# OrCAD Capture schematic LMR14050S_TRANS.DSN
size Custom; title: 40V, 5A SIMPLE SWITCHER®, 2.2MHz Step-Down Regulator; note: DATASHEET:
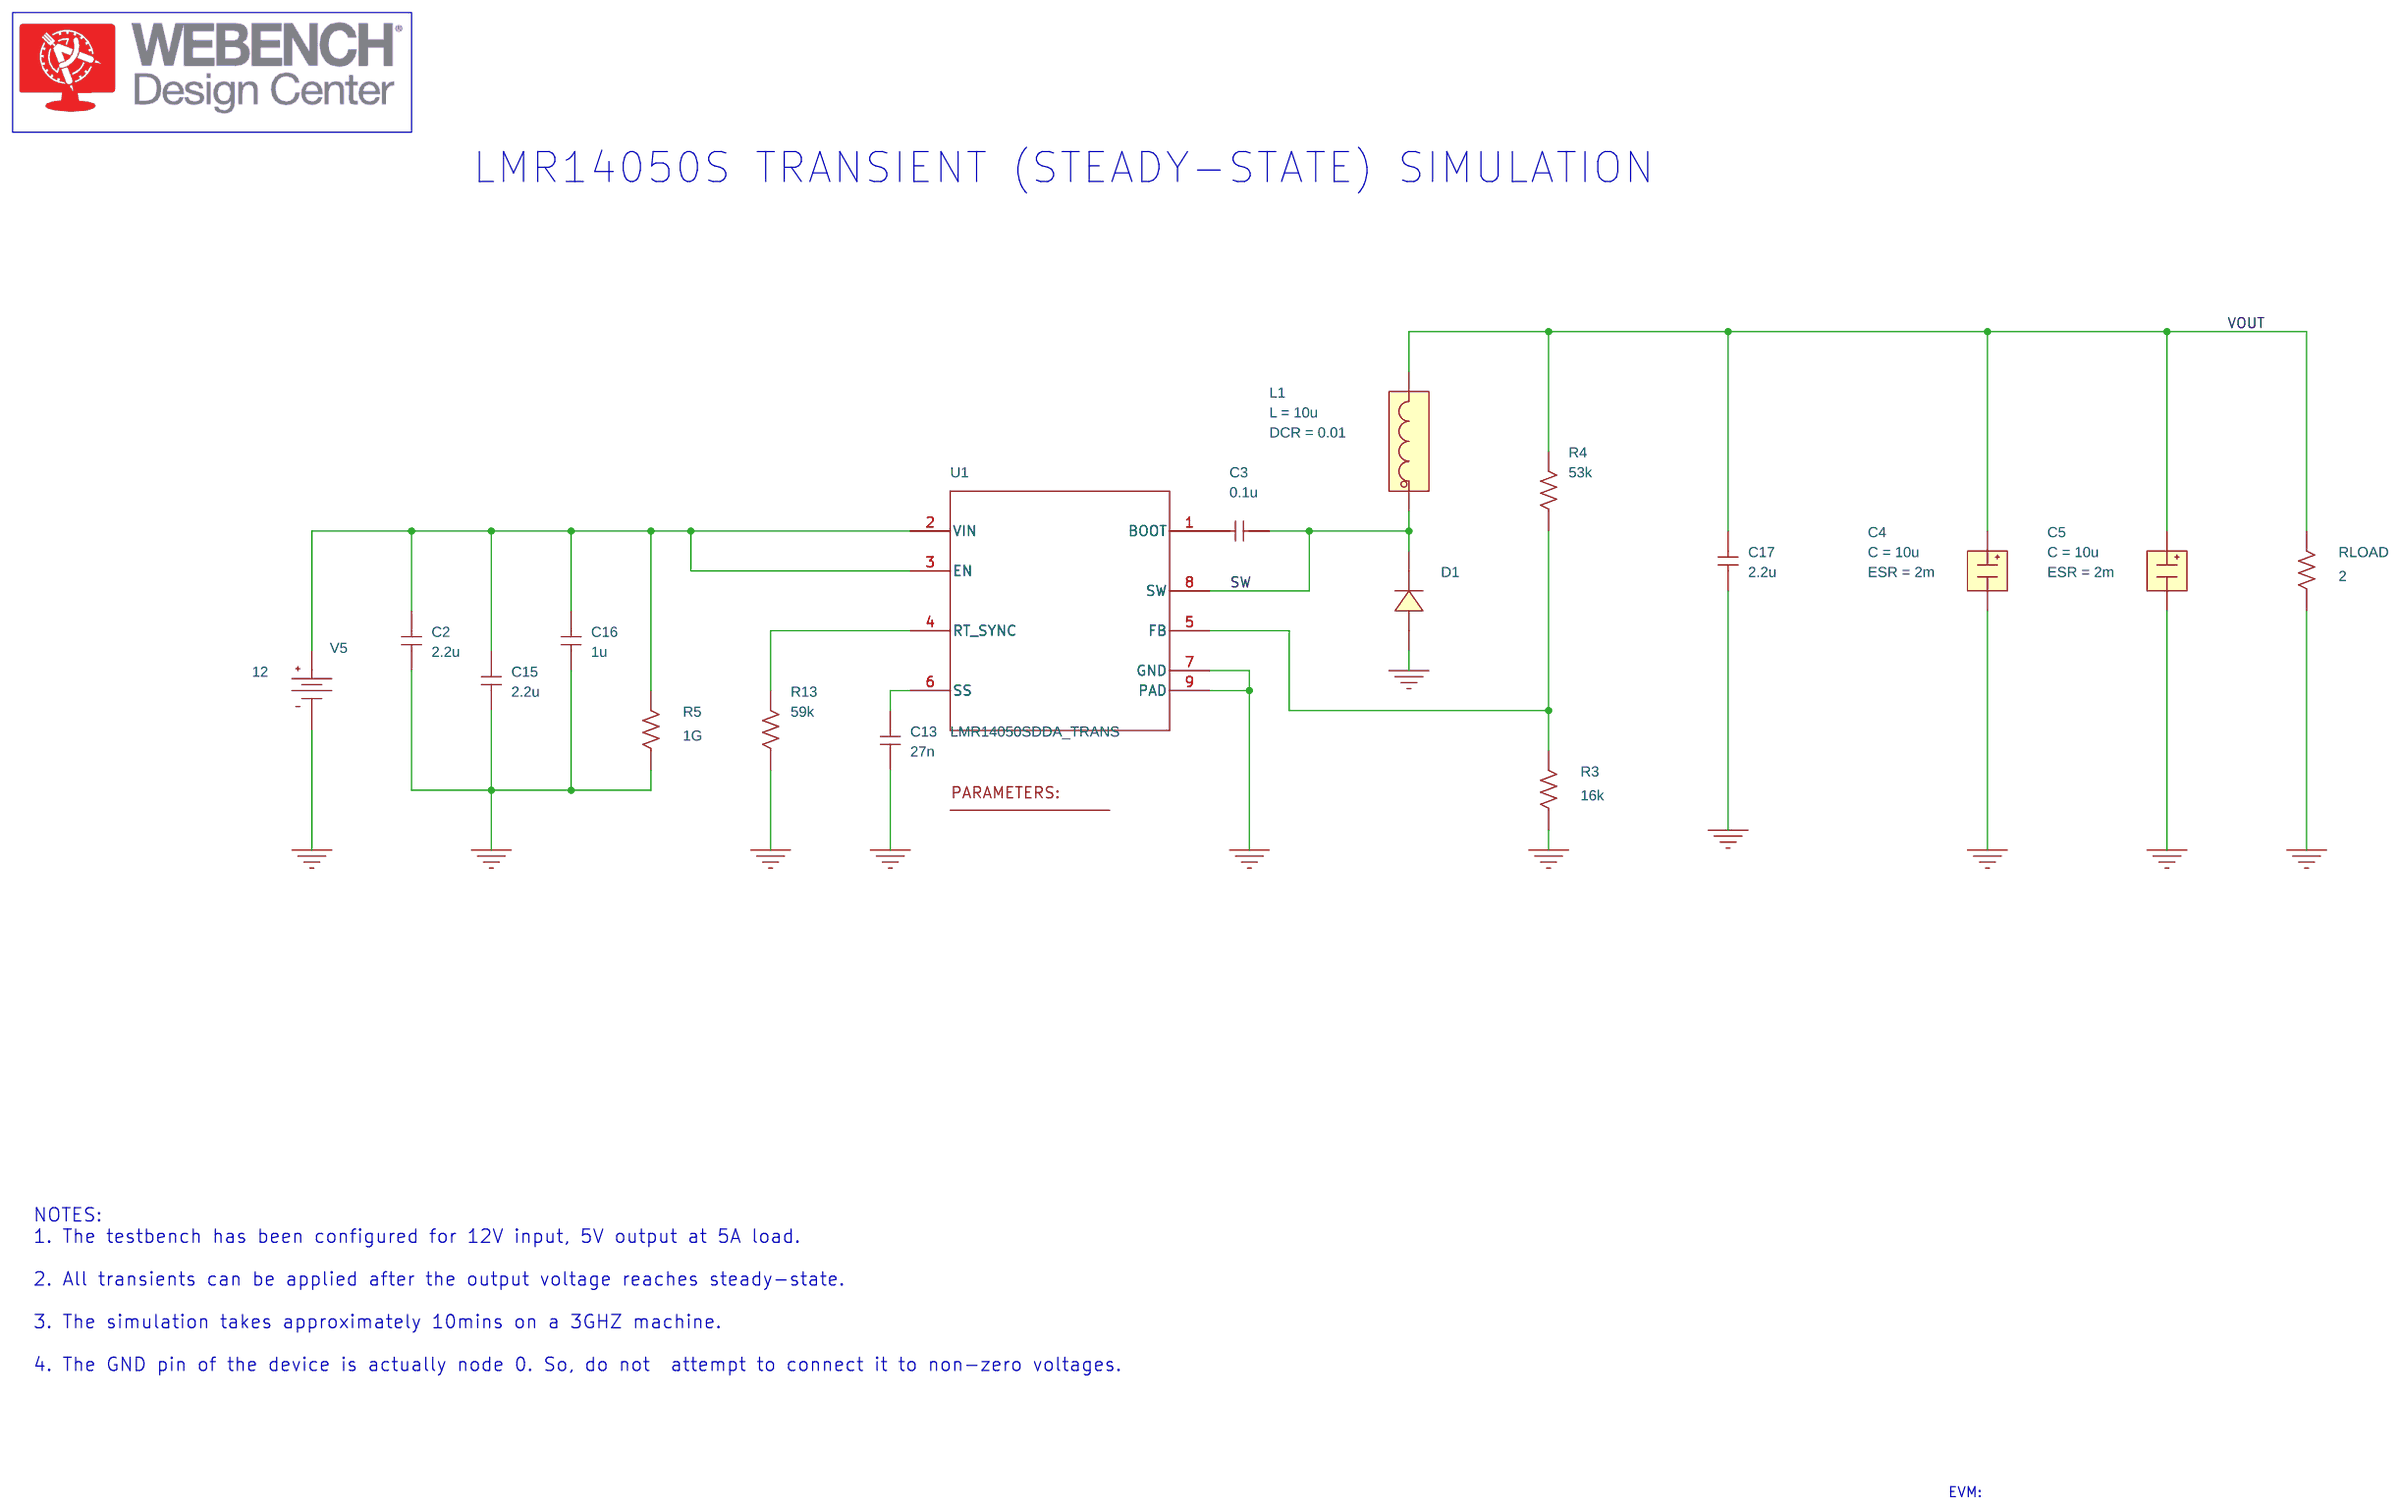
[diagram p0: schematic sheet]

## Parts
1  PARAM
C2  2.2u  [RAD/CK05]
C3  0.1u  [RAD/CK05]
C4  CESR
C5  CESR
C13  27n  [RAD/CK05]
C15  2.2u  [RAD/CK05]
C16  1u  [RAD/CK05]
C17  2.2u  [RAD/CK05]
D1  D_D1
L1  LDCR
R3  16k  [AX/RC05]
R4  53k  [AX/RC05]
R5  1G  [AX/RC05]
R13  59k  [AX/RC05]
RLOAD  2  [AX/RC05]
U1  LMR14050SDDA_TRANS  [DDA0008E]
V5  VDC

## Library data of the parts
1 = PARAM
C2 C15-C17 = C: IC: 12
C3 C13 = C
C4 C5 = CESR: C: 10u; ESR: 2m; IC: 3.2; PSpiceTemplate: X^@REFDES %IN %OUT @MODEL PARAMS:  ?C|C=@C||C=100u|  ?ESR|ESR=@ESR||ESR=0.01| ?X|X=@X||X=2|  ?IC|IC=@IC||IC=2|; X: 1
D1 = D_D1
L1 = LDCR: DCR: 0.01; IC: 0; L: 10u; PSpiceTemplate: X^@REFDES %IN %OUT @MODEL PARAMS:  ?L|L=@L||L=1u|  ?DCR|DCR=@DCR||DCR=0.01| ?IC|IC=@IC||IC=0|
R3-R5 R13 RLOAD = R
U1 = LMR14050SDDA_TRANS: PSpiceTemplate: X^@REFDES %BOOT %VIN %EN %RT_SYNC %FB %SS %GND %SW %PAD @MODEL
V5 = VDC: DC: 12

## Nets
0: C2.1 C4.3(OUT) C5.3(OUT) C13.1 C15.1 C16.1 C17.1 D1.2(A) R3.1 R5.1 R13.1 RLOAD.1 U1.7(GND) U1.9(PAD) V5.1(-)
SW: C3.1 D1.1(C) L1.1(IN) U1.8(SW)
VOUT: C4.1(IN) C5.1(IN) C17.2 L1.3(OUT) R4.2 RLOAD.2
N7516999: C13.2 U1.6(SS)
N7517075: C2.2 C15.2 C16.2 R5.2 U1.2(VIN) U1.3(EN) V5.0(+)
N7517137: R3.2 R4.1 U1.5(FB)
N14557517: R13.2 U1.4(RT_SYNC)
N16725417: C3.2 U1.1(BOOT)

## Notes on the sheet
- LMR14050S TRANSIENT (STEADY-STATE) SIMULATION
- NOTES:
  1. The testbench has been configured for 12V input, 5V output at 5A load.
  2. All transients can be applied after the output voltage reaches steady-state.
  3. The simulation takes approximately 10mins on a 3GHZ machine.
  4. The GND pin of the device is actually node 0. So, do not  attempt to connect it to non-zero voltages.
- EVM:
